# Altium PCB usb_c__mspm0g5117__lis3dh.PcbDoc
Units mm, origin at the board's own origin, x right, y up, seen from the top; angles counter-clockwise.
Board outline 68 x 40 mm, 2 copper layers (Top, Bottom), stack 0 mm thick; 34 components, 28 nets, 186 pads, 63 vias.
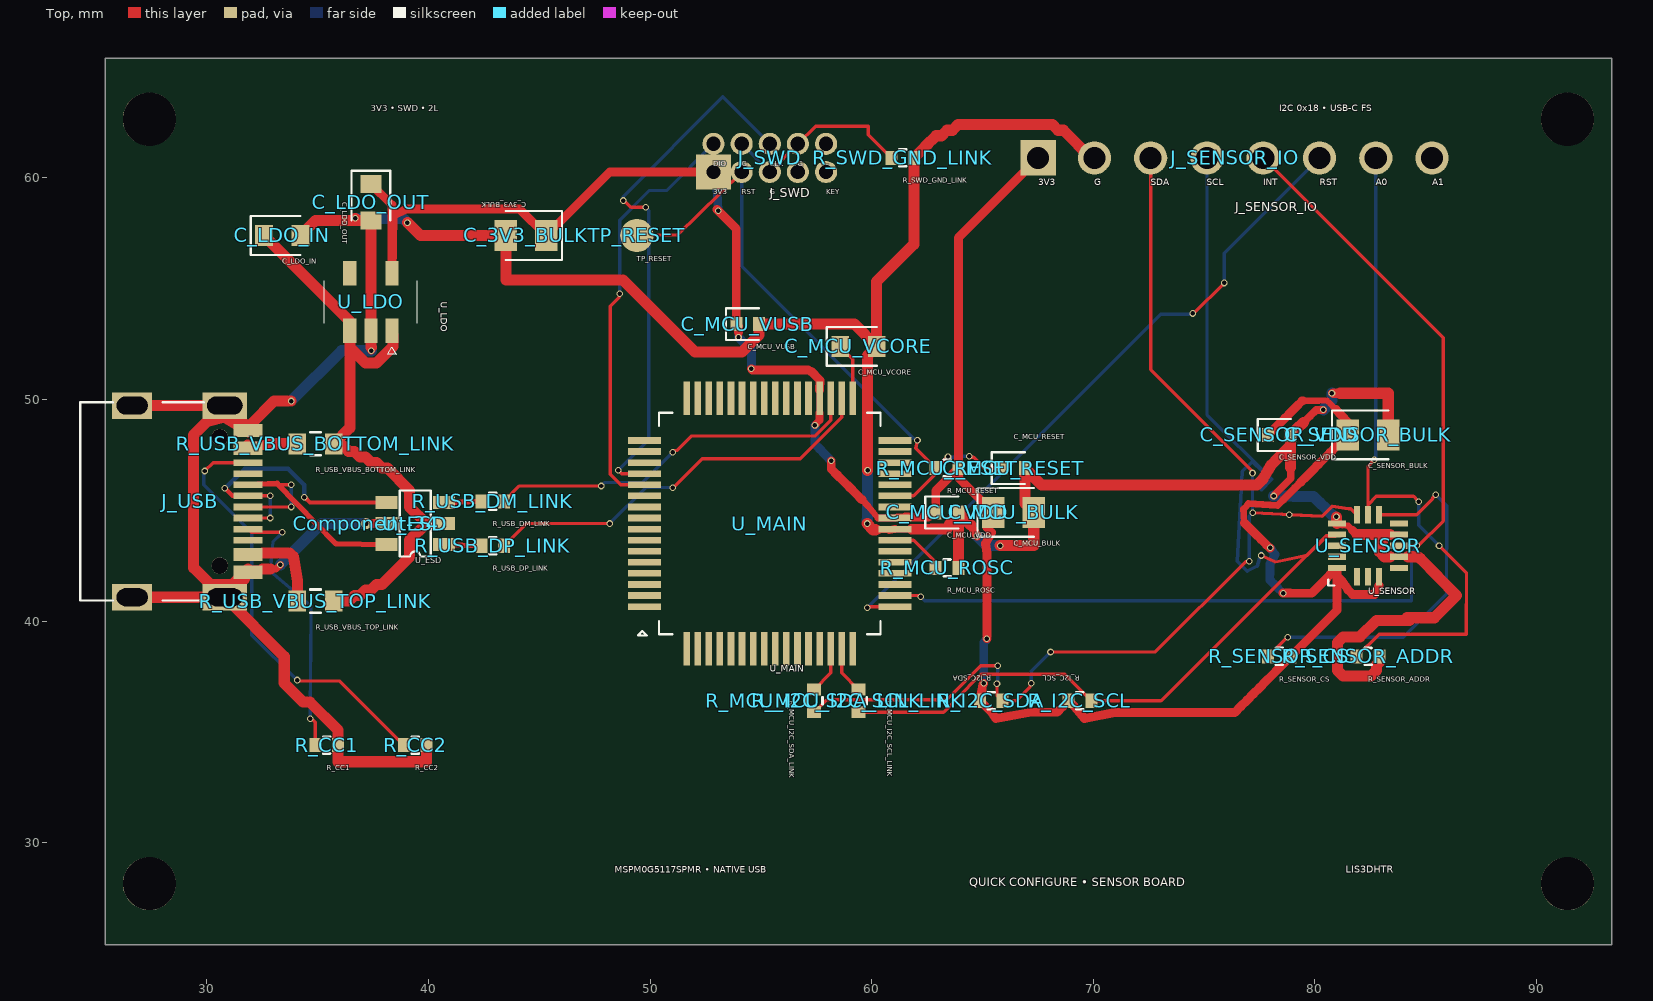
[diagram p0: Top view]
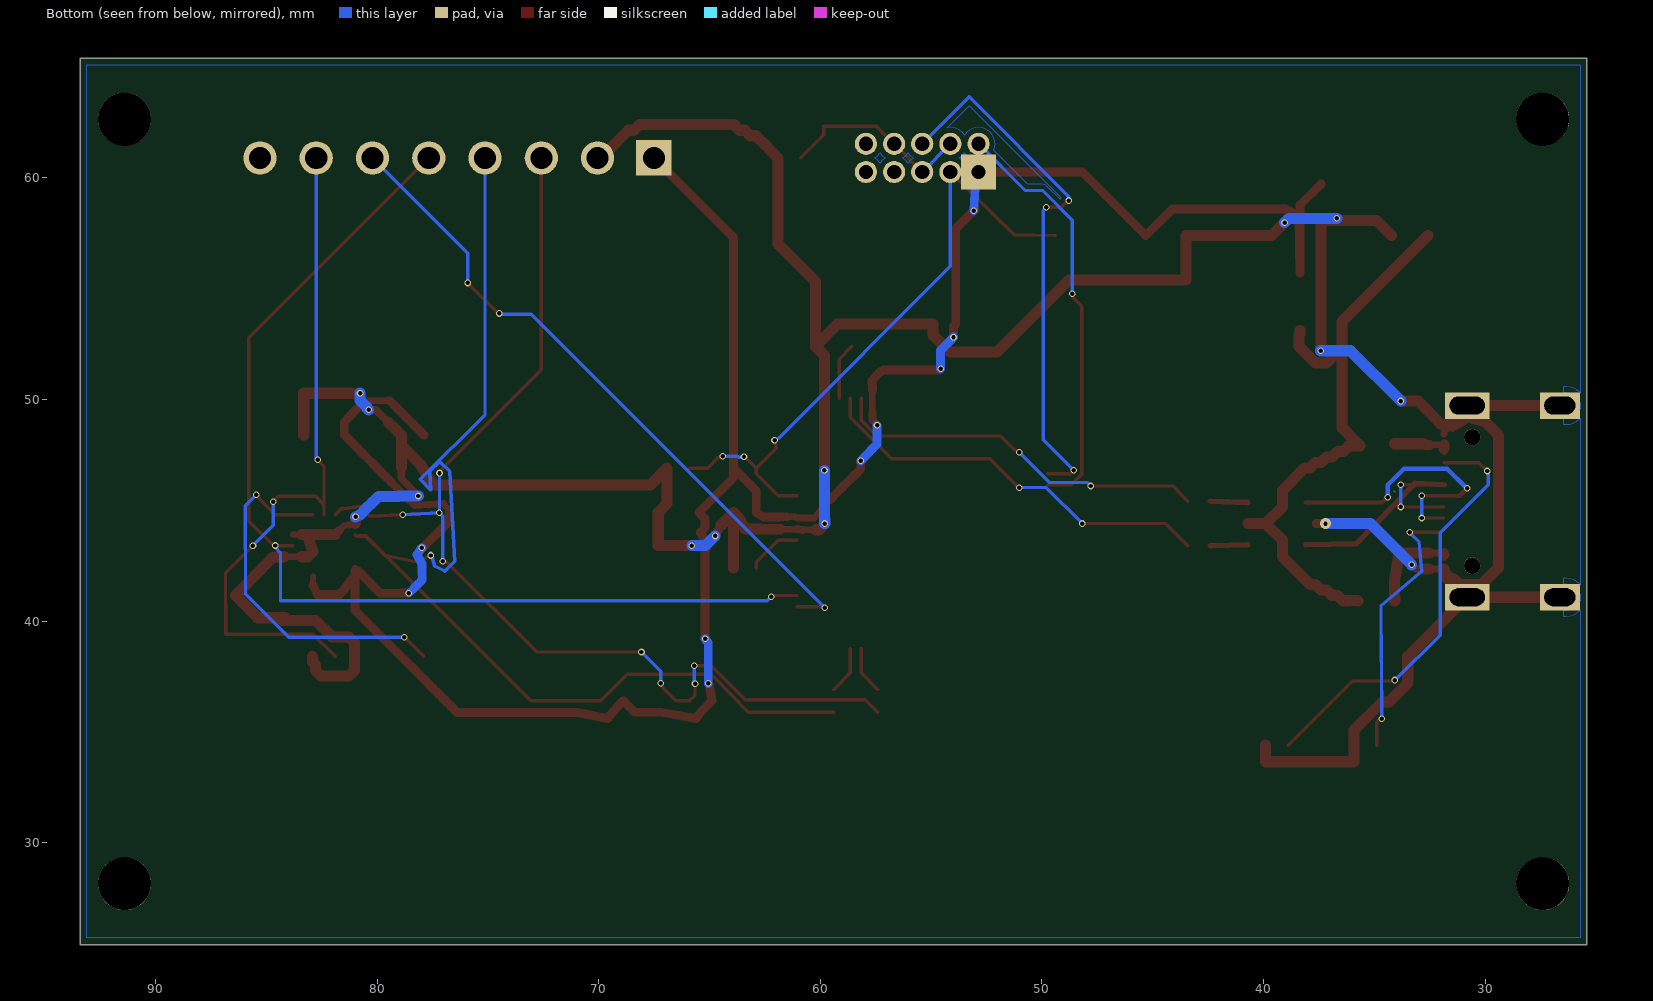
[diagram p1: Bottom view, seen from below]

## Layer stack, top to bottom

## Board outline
25.4,65.4 93.4,65.4 93.4,25.4 25.4,25.4

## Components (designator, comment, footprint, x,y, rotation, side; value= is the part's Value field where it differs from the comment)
C_3V3_BULK "" TSCIRCUIT-2.8500x1.4000mm 44.4,57.4 r180 top
C_LDO_IN "" TSCIRCUIT-2.4500x0.9500mm 33.4,57.4 r0 top
C_LDO_OUT "" TSCIRCUIT-0.9500x2.4500mm 37.4,58.9 r270 top
C_MCU_BULK "" TSCIRCUIT-2.8500x1.4000mm 66.4,44.9 r0 top
C_MCU_RESET "" TSCIRCUIT-1.5600x0.6400mm 66.4,46.9 r0 top
C_MCU_VCORE "" TSCIRCUIT-2.4500x0.9500mm 59.4,52.4 r0 top
C_MCU_VDD "" TSCIRCUIT-1.5600x0.6400mm 63.4,44.9 r0 top
C_MCU_VUSB "" TSCIRCUIT-1.5600x0.6400mm 54.4,53.4 r0 top
C_SENSOR_BULK "" TSCIRCUIT-2.8500x1.4000mm 82.4,48.4 r0 top
C_SENSOR_VDD "" TSCIRCUIT-1.5600x0.6400mm 78.4,48.4 r0 top
Component-34 "" TSCIRCUIT-0.5000x0.5000mm 37.2,44.4 r0 top
J_SENSOR_IO "" TSCIRCUIT-19.2800x1.5000mm 76.4,60.9 r0 top
J_SWD "" TSCIRCUIT-6.0800x2.2700mm 55.4,60.9 r0 top
J_USB "" TSCIRCUIT-6.7732x9.8502mm 29.112,45.4 r90 top
R_CC1 "" TSCIRCUIT-1.5600x0.6400mm 35.4,34.4 r0 top
R_CC2 "" TSCIRCUIT-1.5600x0.6400mm 39.4,34.4 r0 top
R_I2C_SCL "" TSCIRCUIT-1.5600x0.6400mm 69.4,36.4 r180 top
R_I2C_SDA "" TSCIRCUIT-1.5600x0.6400mm 65.4,36.4 r180 top
R_MCU_I2C_SCL_LINK "" TSCIRCUIT-0.6400x1.5600mm 59.4,36.4 r270 top
R_MCU_I2C_SDA_LINK "" TSCIRCUIT-0.6400x1.5600mm 57.4,36.4 r270 top
R_MCU_RESET "" TSCIRCUIT-1.5600x0.6400mm 63.4,46.9 r0 top
R_MCU_ROSC "" TSCIRCUIT-1.5600x0.6400mm 63.4,42.4 r0 top
R_SENSOR_ADDR "" TSCIRCUIT-1.5600x0.6400mm 82.4,38.4 r0 top
R_SENSOR_CS "" TSCIRCUIT-1.5600x0.6400mm 78.4,38.4 r0 top
R_SWD_GND_LINK "" TSCIRCUIT-1.5600x0.6400mm 61.4,60.9 r0 top
R_USB_DM_LINK "" TSCIRCUIT-1.5600x0.6400mm 42.9,45.4 r0 top
R_USB_DP_LINK "" TSCIRCUIT-1.5600x0.6400mm 42.9,43.4 r0 top
R_USB_VBUS_BOTTOM_LINK "" TSCIRCUIT-2.4500x0.9500mm 34.9,48 r0 top
R_USB_VBUS_TOP_LINK "" TSCIRCUIT-2.4500x0.9500mm 34.9,40.9 r0 top
TP_RESET "" TSCIRCUIT-1.5000x1.5000mm 49.4,57.4 r0 top
U_ESD "" TSCIRCUIT-3.6000x2.5000mm 39.4,44.4 r0 top
U_LDO "" TSCIRCUIT-2.5000x3.7000mm 37.4,54.4 r270 top
U_MAIN "" TSCIRCUIT-12.8000x12.8000mm 55.4,44.4 r0 top
U_SENSOR "" TSCIRCUIT-3.6001x3.5998mm 82.4,43.4 r0 top

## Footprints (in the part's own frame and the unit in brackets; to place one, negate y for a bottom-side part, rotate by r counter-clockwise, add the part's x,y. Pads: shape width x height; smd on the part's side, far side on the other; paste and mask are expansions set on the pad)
TSCIRCUIT-0.5000x0.5000mm [mm]
TSCIRCUIT-0.6400x1.5600mm [mm]
  rect 0.54x0.64 smd: 1(-0.51,0) 2(0.51,0)
  silkscreen extent -0.15,-0.38 0.15,0.38
TSCIRCUIT-0.9500x2.4500mm [mm]
  rect 0.8x0.95 smd: 1(-0.825,0) 2(0.825,0)
  silkscreen extent -1.43,-0.87 0.82,0.88
TSCIRCUIT-1.5000x1.5000mm [mm]
  round 1.5 smd: 1(0,0)
TSCIRCUIT-1.5600x0.6400mm [mm]
  rect 0.54x0.64 smd: 1(-0.51,0) 2(0.51,0)
  silkscreen extent -0.98,-0.72 0.51,0.72
TSCIRCUIT-2.4500x0.9500mm [mm]
  rect 0.8x0.95 smd: 1(-0.825,0) 2(0.825,0)
  silkscreen extent -1.42,-0.87 0.82,0.87
TSCIRCUIT-2.5000x3.7000mm [mm]
  rect 1.1x0.6 smd: 1(1.3,0.95) 2(1.3,0) 3(1.3,-0.95) 4(-1.3,-0.95) 5(-1.3,0.95)
  silkscreen extent -0.95,-2.1 2.35,2.1
TSCIRCUIT-2.8500x1.4000mm [mm]
  rect 1.025x1.4 smd: 1(-0.913,0) 2(0.913,0)
  silkscreen extent -1.63,-1.1 0.91,1.1
TSCIRCUIT-3.6000x2.5000mm [mm]
  rect 1x0.6 smd: 1(-1.3,-0.95) 2(-1.3,0) 3(-1.3,0.95) 4(1.3,0.95) 5(1.3,0) 6(1.3,-0.95)
  silkscreen extent -0.7,-1.49 0.7,1.49
TSCIRCUIT-3.6001x3.5998mm [mm]
  rect 0.8x0.28 smd: 1(-1.4,-1) 2(-1.4,-0.5) 3(-1.4,0) 4(-1.4,0.5) 5(-1.4,1) 9(1.4,1) 10(1.4,0.5) 11(1.4,0) 12(1.4,-0.5) 13(1.4,-1)
  rect 0.28x0.8 smd: 6(-0.5,1.4) 7(0,1.4) 8(0.5,1.4) 14(0.5,-1.4) 15(0,-1.4) 16(-0.5,-1.4)
  silkscreen extent -1.8,-1.8 -1.52,-1.52
TSCIRCUIT-6.0800x2.2700mm [mm]
  rect 1.6x1.6 hole 0.65: 1(-2.54,-0.635)
  round 1 hole 0.65: 2(-2.54,0.635) 3(-1.27,0.635) 4(0,0.635) 5(1.27,0.635) 6(2.54,0.635) 7(2.54,-0.635) 8(1.27,-0.635) 9(0,-0.635) 10(-1.27,-0.635)
TSCIRCUIT-6.7732x9.8502mm [mm]
  rect 0.3x1.3 smd: 1(-3.35,-2.737) 2(-3.05,-2.737) 3(-2.55,-2.737) 4(-2.25,-2.737) 5(-1.75,-2.737) 6(-1.25,-2.737) 7(-0.75,-2.737) 8(-0.25,-2.737) 9(0.25,-2.737) 10(0.75,-2.737) 11(1.25,-2.737) 12(1.75,-2.737) 13(2.55,-2.737) 14(2.25,-2.737) 15(3.35,-2.737) 16(3.05,-2.737)
  rect 1.2x2 hole 0.8 slot 1.6 at 90 deg: 17(-4.325,-1.693) 18(4.325,-1.693)
  rect 1.2x1.8 hole 0.8 slot 1.4 at 90 deg: 19(4.325,2.487) 20(-4.325,2.487)
  round 0.75 hole 0.75 unplated: NPTH-1(-2.9,-1.468) NPTH-2(2.9,-1.468)
  silkscreen extent -4.47,-0.75 4.47,4.83
TSCIRCUIT-12.8000x12.8000mm [mm]
  rect 1.5x0.3 smd: 1(-5.65,-3.75) 2(-5.65,-3.25) 3(-5.65,-2.75) 4(-5.65,-2.25) 5(-5.65,-1.75) 6(-5.65,-1.25) 7(-5.65,-0.75) 8(-5.65,-0.25) 9(-5.65,0.25) 10(-5.65,0.75) 11(-5.65,1.25) 12(-5.65,1.75) 13(-5.65,2.25) 14(-5.65,2.75) 15(-5.65,3.25) 16(-5.65,3.75) 33(5.65,3.75) 34(5.65,3.25) 35(5.65,2.75) 36(5.65,2.25) 37(5.65,1.75) 38(5.65,1.25) 39(5.65,0.75) 40(5.65,0.25) 41(5.65,-0.25) 42(5.65,-0.75) 43(5.65,-1.25) 44(5.65,-1.75) 45(5.65,-2.25) 46(5.65,-2.75) 47(5.65,-3.25) 48(5.65,-3.75)
  rect 0.3x1.5 smd: 17(-3.75,5.65) 18(-3.25,5.65) 19(-2.75,5.65) 20(-2.25,5.65) 21(-1.75,5.65) 22(-1.25,5.65) 23(-0.75,5.65) 24(-0.25,5.65) 25(0.25,5.65) 26(0.75,5.65) 27(1.25,5.65) 28(1.75,5.65) 29(2.25,5.65) 30(2.75,5.65) 31(3.25,5.65) 32(3.75,5.65) 49(3.75,-5.65) 50(3.25,-5.65) 51(2.75,-5.65) 52(2.25,-5.65) 53(1.75,-5.65) 54(1.25,-5.65) 55(0.75,-5.65) 56(0.25,-5.65) 57(-0.25,-5.65) 58(-0.75,-5.65) 59(-1.25,-5.65) 60(-1.75,-5.65) 61(-2.25,-5.65) 62(-2.75,-5.65) 63(-3.25,-5.65) 64(-3.75,-5.65)
  silkscreen extent -5.95,-5.05 5,5
TSCIRCUIT-19.2800x1.5000mm [mm]
  rect 1.6x1.6 hole 1: 1(-8.89,0)
  round 1.5 hole 1: 2(-6.35,0) 3(-3.81,0) 4(-1.27,0) 5(1.27,0) 6(3.81,0) 7(6.35,0) 8(8.89,0)

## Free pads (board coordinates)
  round 2.4 hole 2.4 unplated: NPTH-3(27.4,28.15) NPTH-4(91.4,28.15) NPTH-5(27.4,62.65) NPTH-6(91.4,62.65)

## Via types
v1: diameter 0.3, hole 0.2, Top to Bottom, 62 vias
v2: diameter 0.5, hole 0.2, Top to Bottom, 1 vias

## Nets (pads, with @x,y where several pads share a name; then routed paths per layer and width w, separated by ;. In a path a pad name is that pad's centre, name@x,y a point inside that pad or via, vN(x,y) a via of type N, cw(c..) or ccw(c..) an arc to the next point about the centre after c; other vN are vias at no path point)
".J_SWD > .pin2 to .U_MAIN > .pin12": J_SWD.2 U_MAIN.12 | length 19.1
  Top w0.15: v1(48.63,54.778) 48.61,54.769 48.61,54.624 48.197,54.212 48.197,46.626 48.673,46.15 U_MAIN.12
  Bottom w0.15: v1(48.63,54.778) 48.63,58.094 49.967,59.431 50.756,59.431 J_SWD.2
".J_SWD > .pin4 to .U_MAIN > .pin13": J_SWD.4 U_MAIN.13 | length 24.4
  Top w0.15: v1(48.562,46.802) 48.715,46.65 U_MAIN.13 ; v1(48.784,58.976) 48.856,58.904 48.901,58.904 49.134,58.67 v1(49.802,58.67)
  Bottom w0.15: v1(48.562,46.802) 49.94,48.18 49.94,58.479 49.94,58.532 v1(49.802,58.67) ; v1(48.784,58.976) 48.784,59.159 53.28,63.655 J_SWD.4
".U_MAIN > .pin42 to .R_MCU_ROSC > .pin1": R_MCU_ROSC.1 U_MAIN.42 | length 2.5
  Top w0.15: U_MAIN.42 61.89,43.65 62.89,42.65 R_MCU_ROSC.1
GND: C_3V3_BULK.2 C_LDO_IN.2 C_LDO_OUT.2 C_MCU_BULK.2 C_MCU_RESET.2 C_MCU_VCORE.2 C_MCU_VDD.2 C_MCU_VUSB.2 C_SENSOR_BULK.2 C_SENSOR_VDD.2 J_SENSOR_IO.2 J_USB.1 J_USB.2 J_USB.15 J_USB.16 J_USB.17 J_USB.18 J_USB.19 J_USB.20 R_CC1.2 R_CC2.2 R_MCU_ROSC.2 R_SENSOR_ADDR.2 R_SWD_GND_LINK.2 U_ESD.2 U_LDO.2 U_MAIN.41 U_SENSOR.5 U_SENSOR.10 U_SENSOR.12 | length 178.8
  Top w0.275: J_USB.15@31.467,48.8 31.8,48.6 J_USB.16 ; J_USB.1@31.624,42.125 J_USB.2
  Top w0.28: U_SENSOR.12@83.4,42.9 U_SENSOR.12 83.925,42.9 84.05,42.9 84.175,42.9 U_SENSOR.12@84.2,42.9 ; U_SENSOR.10@83.4,43.9 U_SENSOR.10 U_SENSOR.10@83.4,43.9
  Top w0.3: J_USB.1@31.399,41.9 J_USB.1@31.624,42.125 ; J_USB.1@31.699,41.9 J_USB.1 J_USB.1@31.849,42.2 ; J_USB.15@31.699,48.9 J_USB.15 ; J_USB.2 J_USB.2@31.946,42.332 ; J_USB.16@31.849,48.6 J_USB.15 ; J_USB.15@31.999,48.9 J_USB.15 ; J_USB.2@32.037,42.35 32.13,42.35 32.224,42.35 32.318,42.35 32.411,42.35 J_USB.2@32.499,42.35 ; 60.3,44.12 60.425,44.12 60.55,44.12 60.675,44.12 U_MAIN.41@60.796,44.111 ; U_MAIN.41 61.144,44.15 61.238,44.15 61.331,44.15 61.425,44.15 61.519,44.15 61.613,44.15 61.706,44.15 61.8,44.15 ; U_SENSOR.5@81.25,44.35 81.5,44.3 81.7,44.1
  Top w0.301: J_USB.2@31.946,42.332 J_USB.2@32.037,42.35
  Top w0.325: J_USB.16 J_USB.16@31.849,48.6 ; 32.855,42.35 33.111,42.35 v1(33.314,42.542) ; v1(78.145,45.643) 78.17,45.657 78.179,45.703 78.422,45.947 78.666,46.191 78.91,46.434 78.91,46.926 ; U_SENSOR.5 U_SENSOR.5@81.25,44.35
  Top w0.35: 37.414,52.356 37.414,52.201 v1(37.418,52.197) ; 79.487,48.964 79.776,49.246 80.064,49.528 v1(80.383,49.529) ; v1@80.772,50.286 v1@80.841,50.279
  Top w0.375: U_MAIN.41@60.796,44.111 U_MAIN.41
  Top w0.4: 37.2,44.4 U_ESD.2@37.6,44.4 ; 60.175,44.12 60.3,44.12 ; 64.469,44.341 64.609,44.09 v1(64.749,43.84) ; 81.7,44.1 81.9,43.9
  Top w0.425: v1@80.841,50.279 81.137,50.279
  Top w0.475: 61.8,44.15 62.253,44.15 62.707,44.15
  Top w0.5: J_USB.20 J_USB.17 ; J_USB.19 J_USB.18 ; J_USB.18 30.874,49.725 31.474,49.125 31.699,48.9 ; J_USB.1@31.399,41.9 31.149,41.65 30.15,41.65 29.394,42.406 29.394,42.545 29.394,48.394 30,49 30.8,49.2 31.133,49 J_USB.15@31.467,48.8 ; 31.699,41.9 31.474,41.675 30.874,41.075 J_USB.17 33.488,38.393 33.488,37.195 34.336,36.346 34.639,36.346 35.91,35.075 R_CC1.2 35.91,33.65 39.91,33.65 R_CC2.2 ; J_USB.1@31.849,42.2 J_USB.2 ; 31.999,48.9 33.028,49.929 v1(33.802,49.929) ; 32.499,42.35 32.505,42.35 32.599,42.35 32.855,42.35 ; C_LDO_IN.2 34.9,58.075 C_LDO_OUT.2 ; v1(36.694,58.171) 36.781,58.084 36.9,58.084 36.91,58.075 C_LDO_OUT.2 ; 37.414,52.356 37.4,52.37 37.4,52.735 U_LDO.2 C_LDO_OUT.2 ; v1(39.048,57.98) 39.628,57.4 C_3V3_BULK.2 43.488,55.4 48.775,55.4 52.025,52.15 54.15,52.15 54.91,52.91 C_MCU_VUSB.2 59.225,53.4 C_MCU_VCORE.2 ; v1(59.8,44.4) 60.05,44.12 60.175,44.12 ; v1(59.813,46.799) 59.817,46.803 59.817,46.819 59.817,51.992 C_MCU_VCORE.2 ; 62.707,44.15 63.4,44.15 63.66,44.65 C_MCU_VDD.2 ; R_MCU_ROSC.2 C_MCU_VDD.2 ; 64.469,44.341 64.19,44.62 C_MCU_VDD.2 ; v1(65.8,43.4) 67.312,43.4 C_MCU_BULK.2 66.91,45.303 C_MCU_RESET.2 67.671,46.139 68.168,46.139 77.389,46.139 77.65,46.4 78.019,47.031 78.316,47.329 78.613,47.626 78.91,47.924 C_SENSOR_VDD.2 ; J_SENSOR_IO.2 69.9,60.9 68.65,62.15 68.4,62.15 68.15,62.4 63.9,62.4 63.65,62.15 63.4,62.15 63.15,61.9 62.9,61.9 62.9,61.89 62.838,61.828 62.529,61.519 62.219,61.209 R_SWD_GND_LINK.2 61.91,57.006 60.225,55.321 60.225,54.834 60.225,54.347 60.225,53.86 60.225,53.374 60.225,52.887 C_MCU_VCORE.2 ; 78.91,46.926 78.91,47.417 78.91,47.909 C_SENSOR_VDD.2 ; 79.487,48.964 79.199,48.682 C_SENSOR_VDD.2 ; v1(80.975,44.7) 80.975,44.425 U_SENSOR.5 ; 81.137,50.279 81.434,50.279 83.313,50.279 C_SENSOR_BULK.2 ; 81.9,43.9 83.4,43.9 83.15,43.9 ; R_SENSOR_ADDR.2 82.91,38.16 82.775,38.025 82.775,37.775 82.525,37.525 81.275,37.525 81.025,37.775 81.025,39.025 81.275,39.275 82.025,39.275 82.775,40.025 84.275,40.025 84.15,40.15 85.4,40.15 86.4,41.15 86.4,41.148 ; 83.15,43.9 82.9,43.15 83.15,42.9 83.4,42.9 ; U_SENSOR.12@84.2,42.9 84.3,42.9 84.425,42.9 84.55,42.896 84.676,42.894 84.763,42.812 86.401,41.147
  Bottom w0.5: v1(33.314,42.542) 35.171,44.4 37.2,44.4 ; v1(33.802,49.929) 36.07,52.197 v1(37.418,52.197) ; v1(36.694,58.171) 38.857,58.171 38.918,58.11 v1(39.048,57.98) ; v1(59.8,44.4) 59.8,44.556 59.813,44.569 v1(59.813,46.799) ; v1(64.749,43.84) 64.969,43.62 65.189,43.4 65.494,43.4 v1(65.8,43.4) ; v1(78.145,45.643) 78.595,45.638 79.045,45.632 79.494,45.627 79.944,45.622 80.22,45.347 80.495,45.071 80.77,44.796 80.778,44.796 v1(80.975,44.7) ; v1(80.383,49.529) 80.469,49.623 80.469,49.653 80.767,49.951 v1(80.772,50.286)
MAIN_RESET: C_MCU_RESET.1 J_SWD.10 R_MCU_RESET.1 TP_RESET.1 U_MAIN.38 | length 28.9
  Top w0.15: TP_RESET.1 51.237,57.427 J_SWD.10 ; U_MAIN.38 61.889,45.65 62.89,46.651 R_MCU_RESET.1 ; v1(62.065,48.153) 61.99,47.8 R_MCU_RESET.1 ; v1(63.445,47.412) 63.393,47.403 R_MCU_RESET.1 ; v1(64.41,47.443) 64.459,47.394 64.595,47.394 65.089,46.9 C_MCU_RESET.1
  Bottom w0.15: J_SWD.10 54.13,56.006 61.902,48.234 61.909,48.234 v1(62.065,48.153) ; v1(63.445,47.412) 63.504,47.387 63.684,47.387 63.74,47.443 v1(64.41,47.443)
MCU_I2C_SCL_LOCAL: R_MCU_I2C_SCL_LINK.1 U_MAIN.50 | length 2.2
  Top w0.15: U_MAIN.50 58.65,37.66 R_MCU_I2C_SCL_LINK.1
MCU_I2C_SDA_LOCAL: R_MCU_I2C_SDA_LINK.1 U_MAIN.51 | length 2.2
  Top w0.15: R_MCU_I2C_SDA_LINK.1 58.15,37.66 U_MAIN.51
MSPM0_VCORE: C_MCU_VCORE.1 U_MAIN.32 | length 2.6
  Top w0.15: C_MCU_VCORE.1 59.15,51.825 U_MAIN.32
SENSOR_ADDR0: J_SENSOR_IO.7 R_SENSOR_ADDR.1 U_SENSOR.7 | length 31.5
  Top w0.15: R_SENSOR_ADDR.1 82.897,39.407 86.836,39.407 86.843,42.178 v1(85.605,43.399) ; v1(82.683,47.274) 82.4,46.991 U_SENSOR.7 82.4,45.254 82.775,45.629 84.453,45.629 84.647,45.435 v1(84.691,45.391)
  Bottom w0.15: v1(82.683,47.274) 82.75,47.341 82.75,47.4 J_SENSOR_IO.7 ; v1(84.691,45.391) 84.691,44.313 85.518,43.486 v1(85.605,43.399)
SENSOR_ADDR1: J_SENSOR_IO.8
SENSOR_CS: R_SENSOR_CS.1 U_SENSOR.8 | length 16.9
  Top w0.15: R_SENSOR_CS.1 78.755,39.265 v1(78.771,39.265) ; U_SENSOR.8 84.588,44.8 85.315,45.527 85.315,45.57 v1(85.45,45.706)
  Bottom w0.15: v1(78.771,39.265) 78.779,39.273 78.781,39.273 84,39.275 85.942,41.236 85.957,45.2 v1(85.45,45.706)
SENSOR_INT: J_SENSOR_IO.5 U_MAIN.47 U_SENSOR.11 | length 49
  Top w0.15: U_MAIN.47 62.044,41.15 62.048,41.154 62.16,41.154 v1(62.21,41.104) ; J_SENSOR_IO.5 85.789,52.781 85.79,44.513 84.676,43.4 U_SENSOR.11 v1(84.599,43.41)
  Bottom w0.15: v1(62.21,41.104) 62.392,40.921 84.362,40.918 84.362,43.093 84.594,43.324 84.594,43.394 v1(84.599,43.41)
SENSOR_RESET: J_SENSOR_IO.6 U_MAIN.48 | length 30.9
  Top w0.15: v1(59.8,40.6) 59.806,40.606 59.818,40.606 59.862,40.65 U_MAIN.48 ; v1(74.483,53.882) 74.541,53.882 75.911,55.252 v1(75.918,55.259)
  Bottom w0.15: v1(59.8,40.6) 73.04,53.84 74.447,53.84 74.447,53.846 v1(74.483,53.882) ; v1(75.918,55.259) 75.918,56.608 J_SENSOR_IO.6
SENSOR_SCL: J_SENSOR_IO.4 R_I2C_SCL.1 R_MCU_I2C_SCL_LINK.2 U_SENSOR.4 | length 54.3
  Top w0.15: R_MCU_I2C_SCL_LINK.2 63.242,35.89 64.735,37.424 64.945,37.592 68.718,37.592 R_I2C_SCL.1 73.059,36.4 80.518,43.859 80.959,43.859 U_SENSOR.4 80.931,43.831 80.531,43.831 79.665,42.965 78.223,42.664 v1(77.576,42.958)
  Bottom w0.15: J_SENSOR_IO.4 75.13,49.32 78.057,46.393 77.577,45.914 77.625,46.75 77.175,47.2 76.725,46.75 76.5,42.7 76.95,42.25 77.4,42.475 77.577,43.092 77.577,42.985 v1(77.576,42.958)
SENSOR_SDA: J_SENSOR_IO.3 R_I2C_SDA.1 R_MCU_I2C_SDA_LINK.2 U_SENSOR.6 | length 55.2
  Top w0.15: R_MCU_I2C_SDA_LINK.2 57.962,36.452 59.667,36.449 63.391,36.452 64.919,37.98 65.669,37.98 v1(65.687,37.981) ; v1(65.653,37.176) 65.653,36.657 R_I2C_SDA.1 66.514,36.4 67.148,37.033 67.148,37.148 v1(67.2,37.2) ; v1(68.072,38.604) 72.808,38.604 76.882,42.678 77.013,42.678 v1(77.04,42.705) ; J_SENSOR_IO.3 72.59,51.35 77.151,46.789 77.151,46.713 v1(77.186,46.678) ; v1(77.193,44.887) 80.325,44.725 ; v1(78.85,44.8) 80.325,44.725 ; 80.325,44.725 80.775,45.175 ; 80.325,44.725 80.775,45.175 ; 80.775,45.175 81.515,45.07 81.63,45.07 U_SENSOR.6 81.625,45.075 81.516,45.075 80.775,45.175
  Bottom w0.15: v1(65.653,37.176) 65.714,37.237 65.714,37.244 65.687,37.271 v1(65.687,37.981) ; v1(67.2,37.2) 67.2,37.732 68.055,38.587 v1(68.072,38.604) ; v1(77.04,42.705) 77.04,44.723 77.199,44.881 v1(78.85,44.8) ; v1(77.186,46.678) 77.188,44.958 77.166,44.937 77.166,44.914 v1(77.193,44.887)
swd-ground-1-to-2: J_SWD.3 J_SWD.5 J_SWD.9 R_SWD_GND_LINK.1 | length 9
  Top w0.15: J_SWD.9 J_SWD.5 57.464,62.329 59.841,62.329 59.841,61.949 R_SWD_GND_LINK.1
  Bottom w0.15: J_SWD.3 J_SWD.9
usb-dm-device: R_USB_DM_LINK.1 U_ESD.4 | length 1.7
  Top w0.25: U_ESD.4 R_USB_DM_LINK.1
usb-dm-mcu: R_USB_DM_LINK.2 U_MAIN.30 | length 17.2
  Top w0.15: R_USB_DM_LINK.2 44.105,46.095 v1(47.787,46.095) ; v1(51.019,47.62) 51.093,47.694 51.202,47.694 51.856,48.348 57.432,48.347 58.15,49.066 U_MAIN.30
  Bottom w0.15: v1(47.787,46.095) 47.941,46.249 48.089,46.249 49.648,46.249 v1(51.019,47.62)
usb-dm-port-tie: J_USB.7 J_USB.9 U_ESD.3 | length 12.8
  Top w0.15: J_USB.9@31.349,45.65 31.38,45.65 31.474,45.65 31.568,45.65 31.601,45.65 31.662,45.65 31.755,45.65 J_USB.9 v1(32.85,45.65) ; J_USB.7 v1(32.85,44.65)
  Top w0.162: J_USB.9@31.287,45.65 J_USB.9@31.349,45.65
  Top w0.181: 31.193,45.65 J_USB.9@31.287,45.65
  Top w0.189: 31.156,45.65 31.193,45.65
  Top w0.2: v1(30.806,46) 31.116,45.69 31.156,45.65 ; v1(34.393,45.58) 34.411,45.562 34.438,45.562 34.65,45.35 U_ESD.3
  Bottom w0.15: v1(32.85,44.65) v1(32.85,45.65)
  Bottom w0.2: v1(30.806,46) 30.822,46.016 30.854,46.016 31.714,46.877 33.66,46.877 34.393,46.143 v1(34.393,45.58)
usb-dp-device: R_USB_DP_LINK.1 U_ESD.6 | length 1.7
  Top w0.25: U_ESD.6 R_USB_DP_LINK.1
usb-dp-mcu: R_USB_DP_LINK.2 U_MAIN.31 | length 18.5
  Top w0.15: R_USB_DP_LINK.2 44.41,44.4 v1(48.172,44.4) ; v1(51.019,46.023) 51.035,46.039 51.065,46.039 52.349,47.324 56.782,47.324 58.65,49.192 U_MAIN.31
  Bottom w0.15: v1(48.172,44.4) 48.188,44.416 49.795,46.023 v1(51.019,46.023)
usb-dp-port-tie: J_USB.8 J_USB.10 U_ESD.1 | length 12.3
  Top w0.15: J_USB.8 v1(33.8,45.15) ; J_USB.10 v1(33.8,46.15)
  Top w0.25: J_USB.10 33.167,46.218 35.83,43.481 U_ESD.1
  Bottom w0.15: v1(33.8,45.15) v1(33.8,46.15)
USB_CC1: J_USB.6 R_CC1.1 | length 12.4
  Top w0.15: J_USB.6 31.999,44 v1(33.4,44) ; v1(34.661,35.586) 34.738,35.587 34.89,35.435 R_CC1.1
  Bottom w0.15: v1(33.4,44) 33.369,43.969 32.981,43.582 32.85,42.25 34.699,40.693 v1(34.661,35.586)
USB_CC2: J_USB.12 R_CC2.1 | length 19.4
  Top w0.15: v1(29.901,46.773) 30.278,47.15 J_USB.12 ; v1(34.077,37.337) 34.089,37.293 35.997,37.293 R_CC2.1
  Bottom w0.15: v1(29.901,46.773) 29.858,46.73 29.858,46.142 32.025,43.976 32.025,39.357 v1(34.077,37.337)
USB_VBUS_BOTTOM_LOCAL: J_USB.13 J_USB.14 R_USB_VBUS_BOTTOM_LINK.1 | length 2.5
  Top w0.3: J_USB.14 J_USB.14@31.849,47.8 ; J_USB.13 J_USB.13@32.499,47.95
  Top w0.437: 32.72,47.95 32.769,48
  Top w0.45: 32.499,47.95 32.72,47.95
  Top w0.475: J_USB.13@31.849,47.8 J_USB.13
  Top w0.5: 32.769,48 33.205,48 33.64,48 R_USB_VBUS_BOTTOM_LINK.1
USB_VBUS_TOP_LOCAL: J_USB.3 J_USB.4 R_USB_VBUS_TOP_LINK.1 | length 4.5
  Top w0.275: J_USB.3 J_USB.4@32.064,43.065
  Top w0.3: J_USB.3 31.849,43 J_USB.4 ; J_USB.4@32.064,43.065 32.069,43.07 32.469,43.07 J_USB.4@32.499,43.07
  Top w0.5: 32.499,43.07 33.73,43.07 33.9,42.9 34.08,41.809 34.077,41.355 R_USB_VBUS_TOP_LINK.1
VBUS5: C_LDO_IN.1 R_USB_VBUS_BOTTOM_LINK.2 R_USB_VBUS_TOP_LINK.2 U_ESD.5 U_LDO.1 U_LDO.3 | length 29.4
  Top w0.5: C_LDO_IN.1 36.45,53.525 U_LDO.3 ; R_USB_VBUS_TOP_LINK.2 35.751,40.926 36.232,40.926 36.176,40.926 36.15,40.9 36.4,40.9 36.65,41.15 36.9,41.15 37.15,41.4 37.4,41.4 37.65,41.65 37.9,41.65 39.15,42.9 39.15,43.65 39.9,44.4 ; U_LDO.1 38.35,52.95 38.4,52.9 38.4,52.4 37.65,51.65 37.15,51.65 36.45,52.35 U_LDO.3 ; U_LDO.3 36.45,48.725 R_USB_VBUS_BOTTOM_LINK.2 35.65,47.925 35.65,47.9 36.15,47.9 36.4,47.65 36.65,47.65 36.9,47.4 37.15,47.4 37.4,47.15 37.65,47.15 37.9,46.9 38.15,46.9 39.15,45.9 39.15,45.15 39.9,44.4 ; 39.9,44.4 U_ESD.5 39.9,44.4
VCC_3V3: C_3V3_BULK.1 C_LDO_OUT.1 C_MCU_BULK.1 C_MCU_VDD.1 C_MCU_VUSB.1 C_SENSOR_BULK.1 C_SENSOR_VDD.1 J_SENSOR_IO.1 J_SWD.1 R_I2C_SCL.2 R_I2C_SDA.2 R_MCU_RESET.2 R_SENSOR_CS.2 U_LDO.5 U_MAIN.29 U_MAIN.40 U_SENSOR.1 U_SENSOR.14 | length 119
  Top w0.275: 59.831,45.201 60.053,44.925 60.275,44.65 ; 79.462,49.942 79.82,49.943 80.178,49.943 80.536,49.944 80.679,49.825 80.948,49.544
  Top w0.28: U_SENSOR.1@80.86,42.26 U_SENSOR.1 ; U_SENSOR.14@82.9,41.6 U_SENSOR.14 ; U_SENSOR.1 81,42.26 U_SENSOR.1
  Top w0.3: v1(53.989,52.811) 53.995,53.05 ; U_MAIN.29@57.65,49.393 57.65,49.721 U_MAIN.29 U_MAIN.29@57.65,50.424 ; U_MAIN.40@60.717,44.649 U_MAIN.40 ; 76.81,44.439 76.796,44.755 76.782,45.07 76.903,45.166 76.989,45.304 77.321,45.282 77.654,45.26 77.986,45.237 78.318,45.215 78.581,45.481
  Top w0.306: U_MAIN.40 61.162,44.705 U_MAIN.40@61.509,44.704
  Top w0.307: 60.275,44.65 60.384,44.647 U_MAIN.40@60.717,44.649
  Top w0.312: 59.555,45.478 59.831,45.201
  Top w0.325: v1(57.44,48.836) 57.472,48.866 57.472,48.886 57.65,49.064 ; 76.81,44.439 76.831,44.422
  Top w0.35: 57.65,49.064 U_MAIN.29@57.65,49.393 ; 78.581,45.481 78.844,45.746 79.107,46.011 79.371,46.277
  Top w0.387: U_MAIN.40@61.509,44.704 61.856,44.703
  Top w0.4: C_LDO_OUT.1 38.35,58.775 U_LDO.5 38.4,58.3 39,58.6 44.1,58.6 C_3V3_BULK.1 48.178,60.265 J_SWD.1 ; v1(53.073,58.521) 53.014,58.58 53.89,57.704 C_MCU_VUSB.1 54,53.29 53.995,53.05 ; v1(54.572,51.384) 54.622,51.334 54.627,51.329 54.983,51.329 55.339,51.329 55.695,51.329 56.051,51.329 56.407,51.329 56.763,51.329 57.119,51.329 57.267,51.267 57.667,50.867 U_MAIN.29@57.65,50.424 ; v1(58.174,47.23) 58.174,46.862 58.45,46.585 58.726,46.309 59.002,46.032 59.279,45.755 59.555,45.478 ; 61.856,44.703 62.203,44.701 62.55,44.7 C_MCU_VDD.1 62.89,45.88 R_MCU_RESET.2 ; v1(65.055,37.188) 65.012,37.145 64.951,36.772 R_I2C_SDA.2 65.148,36.142 65.406,35.884 65.6,35.6 67.187,35.884 67.583,35.884 67.979,35.884 68.374,35.884 68.632,36.142 R_I2C_SCL.2 69.155,36.135 69.6,35.6 70.967,35.87 71.353,35.87 71.74,35.87 72.127,35.87 72.513,35.87 72.9,35.87 73.287,35.87 73.673,35.87 74.06,35.87 74.447,35.87 74.833,35.87 75.22,35.87 75.607,35.87 75.993,35.87 76.38,35.87 76.661,36.151 76.942,36.432 77.223,36.713 77.504,36.994 77.785,37.276 78.067,37.557 78.348,37.838 78.629,38.119 R_SENSOR_CS.2 81,40.49 81,42.26 81,42.041 81.21,41.831 81.5,41.4 81.7,41.2 82.7,41.2 82.9,41.6 ; v1(65.198,39.2) 65.198,39.586 65.198,39.973 65.198,40.359 65.198,40.746 65.198,41.132 65.198,41.519 65.198,41.905 65.198,42.291 65.198,42.678 65.198,43.064 65.141,43.5 65.4,44 65.198,44.224 65.198,44.61 65.343,44.755 C_MCU_BULK.1 63.91,46.478 R_MCU_RESET.2 ; J_SENSOR_IO.1 63.912,57.3 R_MCU_RESET.2 ; 76.831,44.422 77.079,44.174 77.326,43.926 77.574,43.678 77.822,43.431 77.829,43.431 v1(77.982,43.303) ; C_SENSOR_VDD.1 78.145,48.655 78.4,48.91 78.655,49.165 78.91,49.42 79.164,49.674 79.419,49.929 79.462,49.942 ; v1(78.57,41.259) 78.891,41.258 79.212,41.256 79.533,41.255 79.854,41.254 80.083,41.483 80.312,41.712 80.541,41.942 80.771,42.171 U_SENSOR.1@80.86,42.26 ; 79.371,46.277 79.634,46.542 79.897,46.807 80.16,47.073 80.423,47.338 80.687,47.603 80.95,47.869 81.213,48.134 81.476,48.399 C_SENSOR_BULK.1 81.488,48.691 81.488,48.982 81.218,49.263 80.948,49.544
  Bottom w0.325: v1@78.536,41.288 v1(78.57,41.259)
  Bottom w0.375: 78.347,41.478 v1@78.536,41.288
  Bottom w0.4: J_SWD.1 52.974,60.151 v1(53.073,58.521) ; v1(53.989,52.811) 54.099,52.701 54.099,52.687 54.335,52.45 54.572,52.213 54.572,51.937 54.572,51.66 v1(54.572,51.384) ; v1(57.44,48.836) 57.44,48.55 57.441,48.263 57.441,47.976 57.651,47.767 57.861,47.557 58.07,47.347 58.07,47.334 v1(58.174,47.23) ; v1(65.055,37.188) 65.055,37.556 65.055,37.925 65.055,38.293 65.055,38.661 65.055,39.03 65.166,39.141 65.166,39.168 v1(65.198,39.2) ; v1(77.982,43.303) 78.2,43 77.975,42.581 77.971,42.221 77.967,41.86 78.157,41.669 78.347,41.478
pads on no net: J_SWD.6 J_SWD.7 J_SWD.8 J_USB.5 J_USB.11 J_USB.NPTH-1 J_USB.NPTH-2 U_LDO.4 U_MAIN.1 U_MAIN.2 U_MAIN.3 U_MAIN.4 U_MAIN.5 U_MAIN.6 U_MAIN.7 U_MAIN.8 U_MAIN.9 U_MAIN.10 U_MAIN.11 U_MAIN.14 U_MAIN.15 U_MAIN.16 U_MAIN.17 U_MAIN.18 U_MAIN.19 U_MAIN.20 U_MAIN.21 U_MAIN.22 U_MAIN.23 U_MAIN.24 U_MAIN.25 U_MAIN.26 U_MAIN.27 U_MAIN.28 U_MAIN.33 U_MAIN.34 U_MAIN.35 U_MAIN.36 U_MAIN.37 U_MAIN.39 U_MAIN.43 U_MAIN.44 U_MAIN.45 U_MAIN.46 U_MAIN.49 U_MAIN.52 U_MAIN.53 U_MAIN.54 U_MAIN.55 U_MAIN.56 U_MAIN.57 U_MAIN.58 U_MAIN.59 U_MAIN.60 U_MAIN.61 U_MAIN.62 U_MAIN.63 U_MAIN.64 U_SENSOR.2 U_SENSOR.3 U_SENSOR.9 U_SENSOR.13 U_SENSOR.15 U_SENSOR.16
copper on no net:
  other v2: 37.2,44.4

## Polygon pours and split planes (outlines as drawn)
GND on Bottom (solid): 93.1,65.1 25.7,65.1 25.7,50.296 25.725,50.326 25.854,50.432 26.001,50.51 26.16,50.559 26.326,50.575 26.476,50.575 26.476,50.325 26.326,50.325 26.209,50.314 26.096,50.279 25.993,50.224 25.902,50.149 25.827,50.058 25.772,49.955 25.747,49.875 25.7,49.875 25.7,49.575 25.747,49.575 25.772,49.496 25.827,49.392 25.902,49.301 25.993,49.226 26.096,49.171 26.209,49.137 26.326,49.125 26.476,49.125 26.476,48.875 26.326,48.875 26.16,48.891 26.001,48.94 25.854,49.018 25.725,49.124 25.7,49.154 25.7,41.646 25.725,41.676 25.854,41.782 26.001,41.86 26.16,41.909 26.326,41.925 26.476,41.925 26.476,41.675 26.326,41.675 26.209,41.663 26.096,41.629 25.993,41.574 25.902,41.499 25.827,41.408 25.772,41.304 25.747,41.225 25.7,41.225 25.7,40.925 25.747,40.925 25.772,40.845 25.827,40.742 25.902,40.651 25.993,40.576 26.096,40.521 26.209,40.486 26.326,40.475 26.476,40.475 26.476,40.225 26.326,40.225 26.16,40.241 26.001,40.29 25.854,40.368 25.725,40.474 25.7,40.504 25.7,25.7 93.1,25.7
GND on Bottom (solid): 53.495,61.14 53.484,61.118 53.399,61.015 53.591,61.015 53.506,61.118
GND on Bottom (solid): 53.61,60.996 53.61,60.804 53.713,60.889 53.735,60.9 53.713,60.911
GND on Bottom (solid): 57.305,61.14 57.294,61.118 57.2,61.005 57.087,60.911 57.065,60.9 57.087,60.889 57.2,60.795 57.294,60.682 57.305,60.66 57.316,60.682 57.41,60.795 57.523,60.889 57.545,60.9 57.523,60.911 57.41,61.005 57.316,61.118
GND on Bottom (solid): 56.035,61.14 56.024,61.118 55.93,61.005 55.817,60.911 55.795,60.9 55.817,60.889 55.93,60.795 56.024,60.682 56.035,60.66 56.046,60.682 56.14,60.795 56.253,60.889 56.275,60.9 56.253,60.911 56.14,61.005 56.046,61.118
GND on Bottom (solid): 53.28,63.266 49.15,59.136 49.154,59.129 49.176,59.054 49.179,59.031 49.772,59.625 49.814,59.659 49.862,59.685 49.913,59.7 49.967,59.706 50.642,59.706 52.173,61.237 52.167,61.248 52.124,61.389 52.11,61.535 52.124,61.681 52.167,61.822 52.236,61.952 52.33,62.065 52.443,62.159 52.573,62.228 52.714,62.271 52.86,62.285 53.006,62.271 53.147,62.228 53.277,62.159 53.39,62.065 53.484,61.952 53.495,61.93 53.506,61.952 53.6,62.065 53.713,62.159 53.843,62.228 53.984,62.271 54.13,62.285 54.275,62.271
GND on Bottom (solid): 34.093,45.88 34.083,45.867 34.075,45.861 34.075,45.82 34.093,45.842

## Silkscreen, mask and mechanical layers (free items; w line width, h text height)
Top Overlay:
  text "3V3 • SWD • 2L" at 37.4,62.9 h0.48
  text "I2C 0x18 • USB-C FS" at 78.4,62.9 h0.5
  text "MSPM0G5117SPMR • NATIVE USB" at 48.4,28.525 h0.52
  text "LIS3DHTR" at 81.4,28.525 h0.55
  text "QUICK CONFIGURE • SENSOR BOARD" at 64.4,27.9 h0.65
